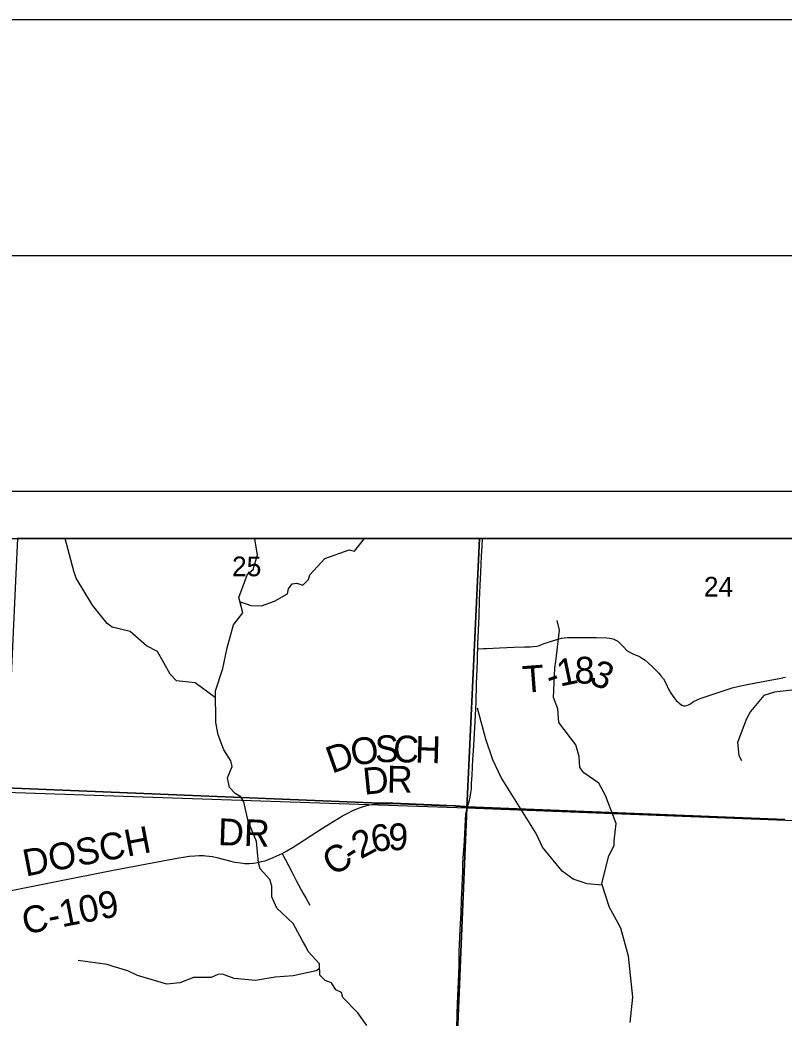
# Model space of a CAD drawing. Extents: x 0 to 34, y 0 to 22.
# Drawn here: x 5.686 to 7.308, y 19.882 to 22 of the extents above; entities that cross this region are included whole.
import ezdxf

# ---------------------------------------------------------------- set-up
doc = ezdxf.new("R2010")
doc.units = 0
for name, color, linetype in [('GM_X_County_Road', 7, 'Continuous'), ('GM_X_County_Road_Text', 7, 'Continuous'), ('GM_X_Minor_River', 7, 'Continuous'), ('GM_X_Rail_Line', 7, 'Continuous'), ('GM_X_Section', 7, 'Continuous'), ('GM_X_Section_Text', 7, 'Continuous'), ('GM_X_Township_Road', 7, 'Continuous'), ('GM_X_Township_Road_Text', 7, 'Continuous'), ('GM_X_Unincorporated_Text', 7, 'Continuous'), ('SH_Border', 7, 'Continuous'), ('SH_Cut_Line', 7, 'Continuous'), ('SH_Data', 7, 'Continuous')]:
    doc.layers.add(name, color=color, linetype=linetype)

msp = doc.modelspace()

# ---------------------------------------------------------------- linework, layer by layer
at = {"layer": 'GM_X_County_Road'}
for points in [[(6.6582, 20.6659), (6.6582, 20.6755), (6.6607, 20.7349), (6.6618, 20.769), (6.6629, 20.8001), (6.6644, 20.828), (6.6661, 20.8621), (6.6673, 20.8838), (6.6682, 20.9)], [(6.6359, 20.3301), (6.6378, 20.3356), (6.6402, 20.3442), (6.6417, 20.3507), (6.6434, 20.36), (6.6443, 20.3687), (6.645, 20.3809), (6.646, 20.397), (6.6467, 20.4155), (6.6474, 20.431), (6.6486, 20.4495), (6.65, 20.4729), (6.6517, 20.4977), (6.6543, 20.552), (6.6555, 20.5917), (6.6565, 20.6228), (6.6571, 20.6414), (6.6576, 20.6533), (6.6582, 20.6659)], [(6.2428, 20.2312), (6.2525, 20.2367), (6.2658, 20.2447), (6.3286, 20.2848), (6.3522, 20.2997), (6.3709, 20.311), (6.3818, 20.317), (6.393, 20.3225), (6.4045, 20.3273), (6.4133, 20.3306), (6.4222, 20.3333), (6.4283, 20.3348), (6.4375, 20.3362), (6.4499, 20.3373), (6.4624, 20.3376), (6.4779, 20.3375), (6.577, 20.3335), (6.6088, 20.3322), (6.6119, 20.3319), (6.6309, 20.3305), (6.6359, 20.3301)], [(6.6134, 19.8601), (6.6144, 19.89), (6.6151, 19.9127), (6.6175, 19.9744), (6.6182, 19.9957), (6.6187, 20.0227), (6.6197, 20.0548), (6.6204, 20.07), (6.6212, 20.0819), (6.6225, 20.1061), (6.6233, 20.1336), (6.6249, 20.1618), (6.6259, 20.1939), (6.6266, 20.2099), (6.628, 20.231), (6.629, 20.2469), (6.6302, 20.2721), (6.6318, 20.3029), (6.6329, 20.3146), (6.6338, 20.3213), (6.6352, 20.328), (6.6359, 20.3301)], [(5.6568, 20.151), (5.7562, 20.1704), (5.8839, 20.1961), (6.0232, 20.2222), (6.0329, 20.2239), (6.0454, 20.2254), (6.0571, 20.2266), (6.0666, 20.2271), (6.0758, 20.227), (6.081, 20.2266), (6.0879, 20.2259), (6.0948, 20.2248), (6.1068, 20.222), (6.1335, 20.215), (6.1425, 20.213), (6.1546, 20.2112), (6.1638, 20.2104), (6.173, 20.2103), (6.1822, 20.211), (6.191, 20.2124), (6.1989, 20.2141), (6.2064, 20.216), (6.2152, 20.2191), (6.2239, 20.2226), (6.2428, 20.2312)]]:
    msp.add_lwpolyline(points, dxfattribs=at)
at = {"layer": 'GM_X_Minor_River'}
for points in [[(6.1014, 20.555), (6.1015, 20.5614), (6.0582, 20.5933), (6.0185, 20.5976), (6.0051, 20.6115), (5.9784, 20.6602), (5.9548, 20.6721), (5.9199, 20.7026), (5.882, 20.7118), (5.871, 20.7197), (5.8401, 20.7585), (5.8057, 20.8158), (5.8007, 20.8302), (5.782, 20.9)], [(6.4227, 19.8663), (6.4033, 19.893), (6.3713, 19.9261), (6.369, 19.9363), (6.3565, 19.9419), (6.3473, 19.957), (6.334, 19.9619), (6.323, 19.9735), (6.3217, 19.9974), (6.2977, 20.0237), (6.2927, 20.0339), (6.2862, 20.046), (6.2663, 20.0826), (6.2317, 20.1153), (6.221, 20.1395), (6.2205, 20.1618), (6.2162, 20.1762), (6.196, 20.1988), (6.1922, 20.2113), (6.1881, 20.2571), (6.1708, 20.2998), (6.1611, 20.341), (6.155, 20.3519), (6.1432, 20.3583), (6.1307, 20.3714), (6.1268, 20.3919), (6.1368, 20.4158), (6.1341, 20.4279), (6.1188, 20.4513), (6.1069, 20.483), (6.1022, 20.5095), (6.1011, 20.5762), (6.117, 20.6236), (6.1262, 20.6676), (6.1392, 20.7166), (6.159, 20.7421), (6.1509, 20.7746), (6.1691, 20.824), (6.1812, 20.8339), (6.1901, 20.8651), (6.1861, 20.89), (6.1846, 20.9)], [(6.1559, 20.7547), (6.1544, 20.7656), (6.1763, 20.7578), (6.1987, 20.7572), (6.2266, 20.7668), (6.2541, 20.7822), (6.2559, 20.7932), (6.2642, 20.8035), (6.274, 20.8047), (6.2869, 20.801), (6.2989, 20.8124), (6.3011, 20.8226), (6.3331, 20.8573), (6.3848, 20.8755), (6.3961, 20.8729), (6.4177, 20.9)], [(6.9813, 19.8728), (6.9874, 19.9262), (6.9782, 20.0137), (6.9616, 20.0726), (6.9558, 20.0836), (6.9375, 20.1164), (6.9213, 20.1667), (6.9353, 20.2244), (6.9476, 20.2491), (6.9476, 20.2585), (6.9519, 20.2953), (6.9288, 20.3546), (6.9147, 20.3807), (6.8832, 20.4028), (6.8748, 20.4137), (6.8731, 20.4372), (6.8658, 20.4621), (6.8303, 20.5093), (6.8282, 20.5384), (6.8186, 20.5626), (6.8217, 20.6243), (6.8235, 20.6384), (6.8318, 20.7055), (6.8267, 20.7259)], [(7.6538, 20.4297), (7.6424, 20.4387), (7.6026, 20.4559), (7.5878, 20.4679), (7.5687, 20.4928), (7.5543, 20.4938), (7.526, 20.4894), (7.4806, 20.4959), (7.4585, 20.5178), (7.4486, 20.5328), (7.4364, 20.5445), (7.4125, 20.5534), (7.3777, 20.5528), (7.3622, 20.5554), (7.3246, 20.5782), (7.3, 20.5754), (7.2879, 20.5734), (7.2649, 20.5668), (7.2371, 20.5325), (7.2282, 20.5173), (7.2095, 20.4672), (7.2124, 20.4392), (7.2181, 20.4286)], [(6.9221, 20.1641), (6.8903, 20.1672), (6.8603, 20.1769), (6.8372, 20.1941), (6.7952, 20.245), (6.7822, 20.2741), (6.7077, 20.3929), (6.6901, 20.4299), (6.6751, 20.4737), (6.6573, 20.5395)], [(6.3223, 19.9867), (6.3146, 19.9822), (6.2663, 19.9716), (6.2281, 19.9691), (6.1861, 19.9616), (6.1407, 19.9658), (6.1161, 19.9755), (6.1063, 19.9747), (6.0923, 19.9685), (6.0545, 19.9683), (6.0254, 19.9571), (5.9978, 19.9538), (5.9353, 19.9723), (5.9152, 19.9821), (5.8841, 19.9917), (5.8712, 19.9961), (5.8099, 20.0041)]]:
    msp.add_lwpolyline(points, dxfattribs=at)
at = {"layer": 'GM_X_Rail_Line'}
for points in [[(8.9, 20.9), (5.68, 20.9)], [(5.6557, 20.3708), (6.4497, 20.3378), (6.4622, 20.3382), (6.4777, 20.338), (6.5768, 20.334), (6.6086, 20.3327), (6.6117, 20.3325), (6.6307, 20.331), (6.6357, 20.3306), (7.3096, 20.3035)], [(7.3096, 20.3035), (6.6357, 20.3306), (6.6307, 20.331), (6.6117, 20.3325), (6.6086, 20.3327), (6.5768, 20.334), (6.4777, 20.338), (6.4622, 20.3382), (6.4497, 20.3378), (5.6557, 20.3708)]]:
    msp.add_lwpolyline(points, dxfattribs=at)
at = {"layer": 'GM_X_Section'}
for points in [[(5.6562, 20.3612), (6.6348, 20.3279), (6.5918, 19.2905), (5.6189, 19.331), (5.6549, 20.3275)], [(6.6348, 20.3279), (7.6587, 20.2884), (7.6132, 19.2594), (6.5918, 19.2905)]]:
    msp.add_lwpolyline(points, close=True, dxfattribs=at)
at = {"layer": 'GM_X_Township_Road'}
for points in [[(6.6582, 20.6659), (6.6701, 20.6662), (6.6763, 20.6666), (6.7042, 20.6679), (6.7353, 20.669), (6.757, 20.6698), (6.7694, 20.6702), (6.7758, 20.6704), (6.7837, 20.6716), (6.7887, 20.673), (6.797, 20.6761), (6.8142, 20.6821), (6.826, 20.6857), (6.8356, 20.6881), (6.8415, 20.6893), (6.8474, 20.6894), (6.8567, 20.6897), (6.8815, 20.6898), (6.8939, 20.6897), (6.9094, 20.6894), (6.9317, 20.689), (6.9383, 20.6885), (6.9415, 20.6876), (6.9444, 20.6869), (6.9472, 20.6859), (6.9498, 20.6847), (6.9527, 20.6832), (6.9551, 20.6816), (6.9594, 20.6776), (6.9678, 20.6689), (6.9737, 20.663), (6.9781, 20.6599), (6.9859, 20.6558), (7.0015, 20.6491), (7.0079, 20.6452), (7.013, 20.6417), (7.0197, 20.6362), (7.0294, 20.627), (7.036, 20.6204), (7.0423, 20.6137), (7.0467, 20.6086), (7.0519, 20.6017), (7.0577, 20.591), (7.0629, 20.58), (7.0677, 20.5714), (7.0711, 20.5663), (7.0751, 20.5613), (7.0792, 20.5563), (7.0825, 20.5529), (7.0856, 20.5503), (7.0882, 20.5482), (7.0913, 20.5462), (7.0949, 20.5449), (7.0981, 20.5448), (7.1021, 20.5456), (7.1054, 20.5467), (7.1081, 20.5482), (7.1122, 20.5511), (7.1162, 20.5537), (7.122, 20.5569), (7.1304, 20.5601), (7.1449, 20.5651), (7.1682, 20.5732), (7.1829, 20.5781), (7.1978, 20.5825), (7.2128, 20.5864), (7.23, 20.5898), (7.2482, 20.5933), (7.2786, 20.5991), (7.3055, 20.6039)], [(7.3111, 20.6049), (7.3055, 20.6039)], [(6.2428, 20.2312), (6.2555, 20.2076), (6.264, 20.1908), (6.2739, 20.1711), (6.2873, 20.1467), (6.2929, 20.1373), (6.3012, 20.1214)]]:
    msp.add_lwpolyline(points, dxfattribs=at)
at = {"layer": 'GM_X_Unincorporated_Text'}
for points in [[(6.6618, 20.9), (5.6806, 20.9), (5.6772, 20.825), (5.6562, 20.3612), (6.6348, 20.3279)], [(7.6858, 20.9), (6.6618, 20.9), (6.6348, 20.3279), (7.6587, 20.2884)]]:
    msp.add_lwpolyline(points, close=True, dxfattribs=at)
at = {"layer": 'SH_Border'}
msp.add_lwpolyline([(1.5, 21.5), (33.5, 21.5), (33.5, 0.5), (1.5, 0.5)], close=True, dxfattribs=at)
at = {"layer": 'SH_Cut_Line'}
msp.add_lwpolyline([(0, 0), (34, 0), (34, 22), (0, 22)], close=True, dxfattribs=at)
at = {"layer": 'SH_Data'}
for p, q in [((2, 21), (9, 21)), ((2.1, 20.9), (8.9, 20.9))]:
    msp.add_line(p, q, dxfattribs=at)

# ---------------------------------------------------------------- texts
at = {"layer": 'GM_X_County_Road_Text'}
for s, height, rotation, p in [('O', 0.0568, 9.7845, (6.393, 20.4165)), ('S', 0.0568, 0.9551, (6.44, 20.4248)), ('C', 0.0568, 358.466, (6.4777, 20.4254)), ('H', 0.0568, 358.4668, (6.5243, 20.4242)), ('D', 0.0568, 19.5178, (6.3484, 20.4005)), ('D', 0.0568, 5.6482, (6.4167, 20.3559)), ('R', 0.0568, 359.395, (6.4648, 20.3607)), ('DOSCH', 0.05682, 11.0311, (5.6982, 20.1823)), ('DR', 0.05682, 358.0243, (6.1058, 20.2493)), ('6', 0.0568, 8.9721, (6.4355, 20.2335)), ('9', 0.0568, 358.7665, (6.4674, 20.2388)), ('2', 0.0568, 28.1013, (6.4094, 20.2186)), ('C', 0.0568, 32.2805, (6.3511, 20.1819)), ('-', 0.0568, 32.0683, (6.3905, 20.2068)), ('C-109', 0.05682, 11.0928, (5.6965, 20.0593))]:
    msp.add_text(s, height=height, rotation=rotation, dxfattribs=at).set_placement(p)
at = {"layer": 'GM_X_Section_Text'}
for s, p in [('25', (6.1363, 20.8196)), ('24', (7.1379, 20.7765))]:
    msp.add_text(s, height=0.04186, rotation=0, dxfattribs=at).set_placement(p)
at = {"layer": 'GM_X_Township_Road_Text'}
for s, rotation, p in [('8', 359.393, (6.8632, 20.5921)), ('T', 4.4084, (6.7549, 20.572)), ('1', 11.7878, (6.8324, 20.5853)), ('3', 336.931, (6.8922, 20.5929)), ('-', 18.6794, (6.8122, 20.5784))]:
    msp.add_text(s, height=0.0568, rotation=rotation, dxfattribs=at).set_placement(p)

doc.saveas('drawing.dxf')
